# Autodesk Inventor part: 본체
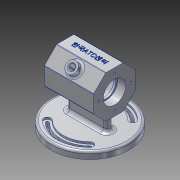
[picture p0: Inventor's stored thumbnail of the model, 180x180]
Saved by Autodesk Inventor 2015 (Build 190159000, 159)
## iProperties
Created: 2017-06
Part Number: 본체
Material: 알루미늄 6061
Document SubType Name: Modeling
Designer: user
Density: 2.7 g/cm^3
Appearance: 알루미늄 - 평지
Author: user
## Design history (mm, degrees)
sketch "스케치1"
  geometry: C1 r 55 at (0, 0); 1 further point
  constraints: 1 centre point, 1 coincident
  dimensions: "d0" = 110 diameter of C1
extrude "돌출1" new body sketch "스케치1" distance "d1" = 10; taper "d2" = 0 deg
sketch "스케치2"
  geometry: L1 (0, 0)-(-30.406, 30.406); L2 (0, 0)-(43, 0); L3 (0, 0)-(30.406, 30.406); A1 r 43 centre (0, 0) between (30.406, 30.406) and (-30.406, 30.406); A2 r 48 centre (0, 0) between (33.941, 33.941) and (-33.941, 33.941); A3 r 38 centre (0, 0) between (26.87, 26.87) and (-26.87, 26.87); A4 r 5 centre (30.406, 30.406) between (26.87, 26.87) and (33.941, 33.941); A5 r 5 centre (-30.406, 30.406) between (-33.941, 33.941) and (-26.87, 26.87); A6 r 43 centre (0, 0) between (-30.406, -30.406) and (30.406, -30.406); A7 r 48 centre (0, 0) between (-33.941, -33.941) and (33.941, -33.941); A8 r 38 centre (0, 0) between (-26.87, -26.87) and (26.87, -26.87); A9 r 5 centre (30.406, -30.406) between (33.941, -33.941) and (26.87, -26.87); A10 r 5 centre (-30.406, -30.406) between (-26.87, -26.87) and (-33.941, -33.941); 1 further point
  constraints: 20 point on circle, 10 centre point, 6 end point, 6 symmetric about line, 4 tangent, 1 coincident, 1 equal length, 1 horizontal, 5 other
  dimensions: "d4" = 135 deg angle of L2 L1; "d5" = 90 deg angle of L3 L1; "d6" = 48 radius of A2; "d7" = 38 radius of A3
extrude "돌출2" cut sketch "스케치2" distance "d8" = 3; taper "d9" = 0 deg
sketch "스케치3"
  geometry: L1 (0, 0)-(-30.406, 30.406); L2 (0, 0)-(43, 0); L3 (0, 0)-(30.406, 30.406); A1 r 43 centre (0, 0) between (30.406, 30.406) and (-30.406, 30.406); A2 r 45 centre (0, 0) between (31.82, 31.82) and (-31.82, 31.82); A3 r 41 centre (0, 0) between (28.991, 28.991) and (-28.991, 28.991); A4 r 2 centre (30.406, 30.406) between (28.991, 28.991) and (31.82, 31.82); A5 r 2 centre (-30.406, 30.406) between (-31.82, 31.82) and (-28.991, 28.991); A6 r 43 centre (0, 0) between (-30.406, -30.406) and (30.406, -30.406); A7 r 45 centre (0, 0) between (-31.82, -31.82) and (31.82, -31.82); A8 r 41 centre (0, 0) between (-28.991, -28.991) and (28.991, -28.991); A9 r 2 centre (30.406, -30.406) between (31.82, -31.82) and (28.991, -28.991); A10 r 2 centre (-30.406, -30.406) between (-28.991, -28.991) and (-31.82, -31.82); 1 further point
  constraints: 20 point on circle, 10 centre point, 6 end point, 6 symmetric about line, 4 tangent, 1 coincident, 1 equal length, 1 horizontal, 5 other
  dimensions: "d10" = 135 deg angle of L2 L1; "d11" = 90 deg angle of L3 L1; "d12" = 4 diameter of A4; "d13" = 43 radius of A1
extrude "돌출3" cut sketch "스케치3" stored distance "d14" = 3; taper "d15" = 0 deg
sketch "스케치4"
  geometry: L1 (-24, 0)-(24, 0); L2 (-24, -5)-(24, -5); L3 (24, 5)-(-24, 5); A1 r 5 centre (-24, 0) between (-24, 5) and (-24, -5); A2 r 5 centre (24, 0) between (24, -5) and (24, 5); 1 further point
  constraints: 8 end point, 4 point on circle, 4 tangent, 2 centre point, 1 horizontal, 1 midpoint, 1 parallel
  dimensions: "d16" = 24 distance of point (0, 0) L1.end; "d17" = 10 diameter of A2
extrude "돌출4" join sketch "스케치4" distance "d18" = 30; taper "d19" = 0 deg
sketch "스케치5"
  geometry: L1 (-30, 49.574)-(-30, 74.426); L2 (-30, 74.426)-(-12.426, 92); L3 (-12.426, 92)-(12.426, 92); L4 (12.426, 92)-(30, 74.426); L5 (30, 74.426)-(30, 49.574); L6 (30, 49.574)-(12.426, 32); L7 (12.426, 32)-(-12.426, 32); L8 (-12.426, 32)-(-30, 49.574); L9 (0, 0)-(0, 62); L10 (0, 92)-(0, 62); 1 further point
  constraints: 20 end point, 2 vertical, 1 coincident, 1 midpoint, 17 other
  dimensions: "d20" = 62 distance of L9.start L9.end; "d21" = 60 distance between parallel lines of L1 L5
extrude "돌출5" join sketch "스케치5" stored distance "d22" = 70; taper "d23" = 0 deg
sketch "스케치6"
  geometry: L1 (74.426, -30)-(49.574, -30) reference; L2 (62, -30)-(62, 36.466); L3 (92, 12.426)-(92, -12.426) reference; L4 (92, 0)-(-12.409, 0); C1 r 16 at (62, 0); 1 further point
  constraints: 4 end point, 2 midpoint, 2 point on line, 1 centre point, 1 horizontal, 1 vertical
  dimensions: "d24" = 32 diameter of C1
extrude "돌출6" cut sketch "스케치6" distance "d25" = 12; taper "d26" = 0 deg
sketch "스케치7"
  geometry: C1 r 14 at (0, 0); C2 r 16 at (0, 0) reference; 1 further point
  constraints: 1 centre point, 1 concentric
  dimensions: "d27" = 28 diameter of C1
extrude "돌출7" cut sketch "스케치7" distance "d28" = 3; taper "d29" = 0 deg
sketch "스케치8"
  geometry: C1 r 25 at (0, 0); C2 r 16 at (0, 0) reference; 1 further point
  constraints: 1 centre point, 1 concentric
  dimensions: "d30" = 50 diameter of C1
extrude "돌출8" cut sketch "스케치8" distance "d31" = 40; taper "d32" = 0 deg
sketch "스케치9"
  geometry: C1 r 16 at (-62, 0); C2 r 14 at (-62, 0) reference; 1 further point
  constraints: 1 centre point, 1 concentric
  dimensions: "d33" = 32 diameter of C1
extrude "돌출9" cut sketch "스케치9" distance "d34" = 12; taper "d35" = 0 deg
sketch "스케치10"
  geometry: C1 r 14 at (0, 0); C2 r 16 at (0, 0) reference; 1 further point
  constraints: 1 centre point, 1 concentric
  dimensions: "d36" = 28 diameter of C1
extrude "돌출10" cut sketch "스케치10" distance "d37" = 3; taper "d38" = 0 deg
sketch "스케치11"
  geometry: L1 (0, 0)-(0, 24.853) reference; L2 (0, 12.426)-(115.197, 12.426); C1 r 8 at (35, 12.426); 1 further point
  constraints: 2 end point, 1 centre point, 1 horizontal, 1 midpoint, 1 point on line
  dimensions: "d39" = 16 diameter of C1; "d40" = 35 distance from line of L1 C1.centre
extrude "돌출11" join sketch "스케치11" distance "d41" = 7; taper "d42" = 0 deg
sketch "스케치12"
  geometry: C1 r 4 at (0, 0); C2 r 8 at (0, 0) reference; 1 further point
  constraints: 1 centre point, 1 concentric
  dimensions: "d43" = 8 diameter of C1
extrude "돌출12" cut sketch "스케치12" distance "d44" = 15; taper "d45" = 0 deg
node "작업 평면1"
sketch "스케치13"
  geometry: L1 (0, 24.853)-(0, 42.426) reference; L2 (70, 42.426)-(0, 42.426) reference; 2 further points
  constraints: 1 other
  dimensions: "d47" = 35 distance from line of L1 point (35, 12.426); "d48" = 30 distance from line of L2 point (35, 12.426)
feature "엠보싱1" sketch "스케치13" dims "d1" = 10, "d2" = 0, "d49" = 0.5, "d50" = 0
sketch "스케치14" dims "d51" = 46
  geometry: L1 (62, 0)-(62, -100.505); C1 r 14 at (62, 0) reference; 6 further points
  constraints: 2 end point, 1 point on line, 1 vertical, 1 vertical alignment, 8 other
  dimensions: "d54" = 360 deg dimension on point (62, 0) point (62, -23) (derived)
hole "구멍1" sketch "스케치14" at (62, -23), (85, 0), (62, 23), (39, 0) diameter "d56" = 3.242; stored, may be unused: countersink angle "d60" = 90 deg, drill point angle "d62" = 118 deg; dims "d57" = 8, "d58" = 4, "d59" = 2, "d61" = 10
fillet "모깎기1" dims "d63" = 3
fillet "모깎기2" dims "d64" = 0.3
chamfer "모따기1" distance "d65" = 1; stored, may be unused: second distance "d66" = 2, angle "d67" = 45 deg
fillet "모깎기3" dims "d68" = 5
fillet "모깎기4" dims "d69" = 1
node "솔리드1"
mirror "대칭1"
